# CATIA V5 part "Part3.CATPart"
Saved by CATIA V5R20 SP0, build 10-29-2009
Part number: UFO中部
Bounding box of the stored display mesh (mm): x -325 to 325, y -325 to 324.994, z 0 to 110
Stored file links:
  C:\Users\16057\Documents\180511420 创意设计\Part3.CATPart
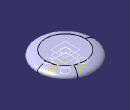
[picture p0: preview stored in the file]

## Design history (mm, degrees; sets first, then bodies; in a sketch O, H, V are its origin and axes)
Body1 (main body)
  Plane1: type Offset, RefPlane xy-plane, Offset 55
  Plane2: type Offset, RefPlane Plane1, Offset 55
  Sketch1 on xy-plane, origin (0, 0, 0), H (1, 0, 0), V (0, 1, 0)
    circle A1 centre (100, 100) radius 45
    circle A2 centre (-100, 100) radius 45
    circle A3 centre (-100, -100) radius 45
    circle A4 centre (100, -100) radius 45
    radius A4 = 45
    radius A3 = 45
    radius A1 = 45
    radius A2 = 45
  Sketch2 on Plane2, origin (0, 0, 110), H (1, 0, 0), V (0, 1, 0)
    circle A1 centre (0, 0) radius 225
    radius A1 = 225
  Sketch3 on Plane1, origin (0, 0, 55), H (1, 0, 0), V (0, 1, 0)
    circle A1 centre (0, 0) radius 325
    radius A1 = 325
  Sketch4 on xy-plane, origin (0, 0, 0), H (1, 0, 0), V (0, 1, 0)
    circle A1 centre (0, 0) radius 225
    radius A1 = 225
  Loft1: solid, Sections (Sketch2; Sketch3; Sketch4)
